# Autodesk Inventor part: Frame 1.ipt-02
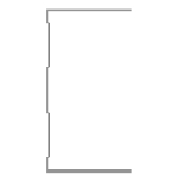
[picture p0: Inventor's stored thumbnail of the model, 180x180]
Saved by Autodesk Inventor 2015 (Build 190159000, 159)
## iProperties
IsCustomPart: 1
Created: 2015-04
Part Number: Frame 1.ipt-02
Material: Aluminum 6061
Description: Kévin Novo
Document SubType Name: Modeling
Standard: Kevin
Designer: suporte
Standards Organization: Kevin
Language: en-US
Size Designation: (Unnamed 2)
Categories: <MemberInstance><Categories><Category DisplayName="Structural Shapes" InternalName="089c4875-fa83-4c05-b084-43b9cc11f5ed" Mnemonic="GRDR"><CategoryParameter Dis
Density: 2.7 g/cm^3
Appearance: Aluminum - Flat
_CCFamilyMember: 2
_CCFamilyDisplayName: Kévin - Kévin Novo
_FrameMemberDoc: Frame Member File
_Version: 15.0.0
_GetPNFromCC: 1
G_W: 50,000 mm
G_H: 75,000 mm
G_L: 2100,000 mm
+DAC06604-79BB-4466-A86F-89A14C131ED5+CUTDETAIL1: Notch
Author: suporte
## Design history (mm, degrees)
node "Start Plane"
node "End Plane"
sketch "Sketch"
  geometry: L1 (24.7, 37.5)-(24.7, 36.9); L2 (24.7, 36.9)-(-24.7, 36.9); L3 (-24.7, -36.9)-(24.7, -36.9); L4 (24.7, -36.9)-(24.7, -37.5); L5 (24.7, -37.5)-(-25.3, -37.5); L6 (-25.3, 37.5)-(24.7, 37.5); L7 (-24.7, 36.9)-(-24.7, 31.9); L8 (-24.7, 31.9)-(-23.3, 30.5); L9 (-23.3, 30.5)-(-23.3, 10.934); L10 (-23.3, 10.934)-(-24.7, 9.534); L11 (-24.7, 9.534)-(-24.7, -9.534); L12 (-24.7, -9.534)-(-23.3, -10.934); L13 (-23.3, -10.934)-(-23.3, -30.5); L14 (-23.3, -30.5)-(-24.7, -31.9); L15 (-24.7, -31.9)-(-24.7, -36.9); L16 (-25.3, -37.5)-(-25.3, -31.651); L17 (-25.3, -31.651)-(-23.9, -30.251); L18 (-23.9, -30.251)-(-23.9, -11.183); L19 (-23.9, -11.183)-(-25.3, -9.783); L20 (-25.3, -9.783)-(-25.3, 9.783); L21 (-25.3, 9.783)-(-23.9, 11.183); L22 (-23.9, 11.183)-(-23.9, 30.251); L23 (-23.9, 30.251)-(-25.3, 31.651); L24 (-25.3, 31.651)-(-25.3, 37.5); L25 (-25.3, 0)-(30.37, 0); 3 further points
  constraints: 50 end point, 10 point on line, 9 parallel, 5 perpendicular, 4 equal length, 3 midpoint, 3 vertical, 2 vertical alignment, 1 collinear, 1 horizontal, 1 horizontal alignment
  dimensions: "d3" = 0.6 distance of L1.start L1.end (= d6); "d5" = 75 distance between parallel lines of L5 L6; "d6" = 0.6 distance between parallel lines of L24 L7 (= d8); "d7" = 0.6 distance between parallel lines of L8 L23 (= d8); "d8" = 0.6 distance between parallel lines of L22 L9 (= d12); "Espessura" = 0.6 distance between parallel lines of L17 L14; "d10" = 0.6 distance between parallel lines of L13 L18 (= Espessura); "d11" = 0.6 distance between parallel lines of L12 L19 (= Espessura); "d12" = 0.6 distance between parallel lines of L21 L10 (= d11); "d13" = 5 distance of L2.end L7.end; "d15" = 135 deg angle of L9 L8; "d16" = 2 distance between parallel lines of L24 L9; "d17" = 50 distance of L6.start L1.start
extrude "Body" join sketch "Sketch" stored distance "d24" = 0.13; taper "d25" = 0 deg
node "Driven Length"
  sketch "Sketch10"
    geometry: L1 (0, 0)-(10, 0) reference
    constraints: 2 end point, 1 horizontal
  workplane "Work Plane7"
  sketch "Sketch11"
    geometry: L1 (-2, 0)-(12, 0) reference; L2 (-2, 2100)-(12, 2100) reference
    dimensions: "d27" = 2100 distance between parallel lines of L1 L2 (derived)
workplane "Work Plane8"
workplane "Work Plane9"
workplane "Work Plane10"
sketch "Sketch12"
  geometry: L1 (24.7, 37.5)-(24.7, 36.9); L2 (24.7, 36.9)-(-24.7, 36.9); L3 (-24.7, 36.9)-(-24.7, 31.9); L4 (-24.7, 31.9)-(-23.3, 30.5); L5 (-23.3, 30.5)-(-23.3, 10.934); L6 (-23.3, 10.934)-(-24.7, 9.534); L7 (-24.7, 9.534)-(-24.7, -9.534); L8 (-24.7, -9.534)-(-23.3, -10.934); L9 (-23.3, -10.934)-(-23.3, -30.5); L10 (-23.3, -30.5)-(-24.7, -31.9); L11 (-24.7, -31.9)-(-24.7, -36.9); L12 (-24.7, -36.9)-(24.7, -36.9); L13 (24.7, -36.9)-(24.7, -37.5); L14 (24.7, -37.5)-(-25.3, -37.5); L15 (-25.3, -37.5)-(-25.3, -31.651); L16 (-25.3, -31.651)-(-23.9, -30.251); L17 (-23.9, -30.251)-(-23.9, -11.183); L18 (-23.9, -11.183)-(-25.3, -9.783); L19 (-25.3, -9.783)-(-25.3, 9.783); L20 (-25.3, 9.783)-(-23.9, 11.183); L21 (-23.9, 11.183)-(-23.9, 30.251); L22 (-23.9, 30.251)-(-25.3, 31.651); L23 (-25.3, 31.651)-(-25.3, 37.5); L24 (-25.3, 37.5)-(24.7, 37.5)
  constraints: 48 end point, 10 point on line
extrude "Extrusion3" cut sketch "Sketch12" stored distance "d36" = 0.13; taper "d37" = 0 deg
body "Solid1"
other parameters: "G_OFFSET_START" = 0 [user parameter; used in 1 equation term], "G_OFFSET_END" = 0 [user parameter; used in 1 equation term], "d22" = 0 (computed from G_OFFSET_START), "G_L" = 2100 (= d27) [user parameter], "d34" = 90 deg
